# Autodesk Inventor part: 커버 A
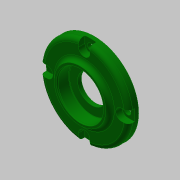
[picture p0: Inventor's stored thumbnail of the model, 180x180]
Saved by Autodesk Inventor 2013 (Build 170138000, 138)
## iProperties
Created: 2019-05
Part Number: 커버 A
Material: 알루미늄 6061
Document SubType Name: Modeling
Designer: mduedu
Density: 2.71 g/cm^3
Mass: 47.9629 g
Surface Area: 85.729 cm^2
Volume: 17.6985 cm^3
Author: mduedu
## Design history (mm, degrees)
sketch "스케치1"
  geometry: C1 r 31 at (0, 0); 1 further point
  constraints: 1 centre point, 1 coincident
  dimensions: "d0" = 62 diameter of C1
extrude "돌출1" new body sketch "스케치1" distance "d1" = 7; taper "d2" = 0 deg
sketch "스케치2"
  geometry: C1 r 18 at (0, 0); 1 further point
  constraints: 1 centre point, 1 coincident
  dimensions: "d3" = 36 diameter of C1
extrude "돌출2" join sketch "스케치2" distance "d4" = 3; taper "d5" = 0 deg
fillet "모깎기1" dims "d6" = 3
sketch "스케치3"
  geometry: C1 r 20 at (0, 0); 1 further point
  constraints: 1 centre point, 1 coincident
  dimensions: "d7" = 40 diameter of C1
extrude "돌출3" join sketch "스케치3" distance "d8" = 4; taper "d9" = 0 deg
sketch "스케치4"
  geometry: C1 r 17 at (0, 0); 1 further point
  constraints: 1 centre point, 1 coincident
  dimensions: "d10" = 34 diameter of C1
extrude "돌출4" cut sketch "스케치4" distance "d11" = 3; taper "d12" = 0 deg
sketch "스케치5"
  geometry: C1 r 16 at (0, 0); 1 further point
  constraints: 1 centre point, 1 coincident
  dimensions: "d13" = 32 diameter of C1
extrude "돌출5" cut sketch "스케치5" distance "d14" = 8.3; taper "d15" = 0 deg
sketch "스케치6"
  geometry: C1 r 10 at (0, 0); 1 further point
  constraints: 1 centre point, 1 coincident
  dimensions: "d16" = 20 diameter of C1
extrude "돌출6" cut sketch "스케치6" stored distance "d17" = 8.3; taper "d18" = 0 deg
fillet "모깎기2" dims "d19" = 0.3
fillet "모깎기3" dims "d20" = 3
fillet "모깎기4" dims "d21" = 3
chamfer "모따기1" distance "d22" = 1; stored, may be unused: second distance "d23" = 2, angle "d24" = 45 deg
sketch "스케치7" dims "d25" = 52
  geometry: L1 (-4, 26)-(-4, 30.741); L2 (4, 26)-(4, 30.741); A1 r 4 centre (0, 26) between (-4, 26) and (4, 26); A2 r 31 centre (0, 0) between (4, 30.741) and (-4, 30.741); 3 further points
  constraints: 4 end point, 4 point on circle, 2 centre point, 2 coincident, 2 tangent, 2 vertical alignment, 1 parallel, 1 vertical, 4 other
  dimensions: "d26" = 8 distance between parallel lines of L2 L1
extrude "돌출7" cut sketch "스케치7" distance "d27" = 4.4; taper "d28" = 0 deg
chamfer "모따기2" distance "d32" = 0.8; stored, may be unused: second distance "d33" = 2, angle "d34" = 30 deg
sketch "스케치8" dims "d36" = 52
  geometry: 6 further points
  constraints: 2 vertical alignment, 1 coincident, 7 other
  dimensions: "d39" = 360 deg dimension on point (0, 0) point (0, 26) (derived)
sketch "스케치9"
  geometry: 4 further points
  constraints: 4 other
hole "구멍1" sketch "스케치9" at (-26, 0), (0, -26), (26, 0), (0, 26) diameter "d41" = 4.5; stored, may be unused: countersink angle "d45" = 90 deg, drill point angle "d47" = 0 deg; dims "d42" = 6, "d43" = 4, "d44" = 2, "d46" = 8
node "솔리드1"
pattern_circular "원형 패턴1" dims angle "d30" = 360 deg
